// Mitsubishi GX Works2 project: Yuwakashi   PLC: Q00J

PROGRAM MAIN
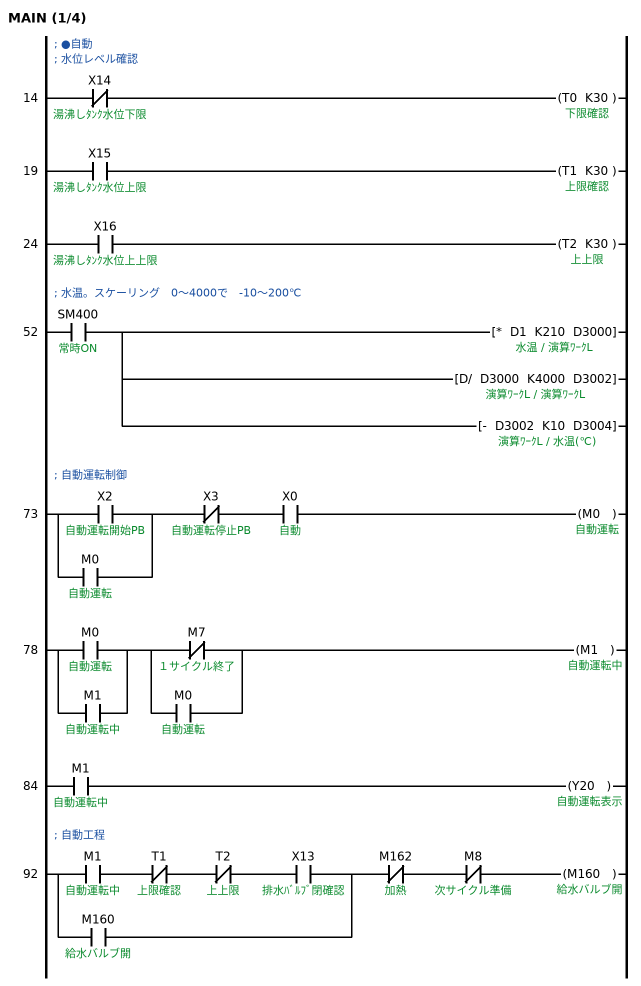
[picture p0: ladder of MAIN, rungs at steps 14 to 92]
; ●自動
; 水位レベル確認
14    LDI     X14  ; 湯沸しﾀﾝｸ水位下限
      OUT     T0 K30  ; 下限確認
19    LD      X15  ; 湯沸しﾀﾝｸ水位上限
      OUT     T1 K30  ; 上限確認
24    LD      X16  ; 湯沸しﾀﾝｸ水位上上限
      OUT     T2 K30  ; 上上限
; 水温。スケーリング　0～4000で　-10～200℃
52    LD      SM400  ; 常時ON
      *       D1 K210 D3000  ; 水温 / 演算ﾜｰｸL
      D/      D3000 K4000 D3002  ; 演算ﾜｰｸL
      -       D3002 K10 D3004  ; 水温(℃)
; 自動運転制御
73    LD      X2  ; 自動運転開始PB
      OR      M0  ; 自動運転
      ANI     X3  ; 自動運転停止PB
      AND     X0  ; 自動
      OUT     M0  ; 自動運転
78    LD      M0  ; 自動運転
      OR      M1  ; 自動運転中
      LDI     M7  ; １サイクル終了
      OR      M0  ; 自動運転
      ANB
      OUT     M1  ; 自動運転中
84    LD      M1  ; 自動運転中
      OUT     Y20  ; 自動運転表示
; 自動工程
92    LD      M1  ; 自動運転中
      ANI     T1  ; 上限確認
      ANI     T2  ; 上上限
      AND     X13  ; 排水ﾊﾞﾙﾌﾞ閉確認
      OR      M160  ; 給水バルブ開
      ANI     M162  ; 加熱
      ANI     M8  ; 次サイクル準備
      OUT     M160  ; 給水バルブ開
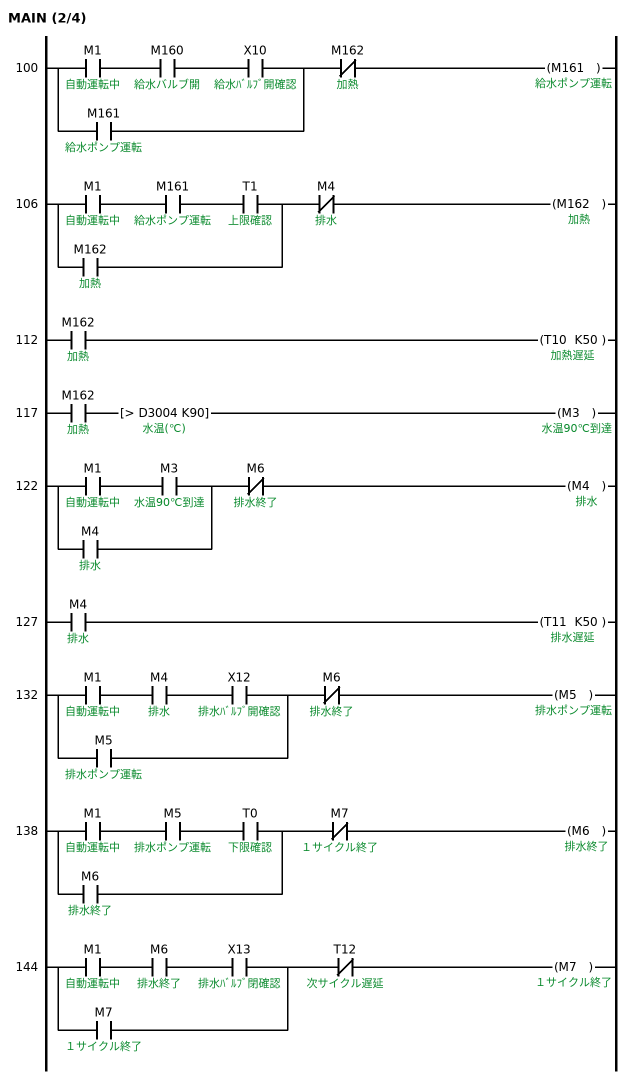
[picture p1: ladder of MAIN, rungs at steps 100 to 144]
100   LD      M1  ; 自動運転中
      AND     M160  ; 給水バルブ開
      AND     X10  ; 給水ﾊﾞﾙﾌﾞ開確認
      OR      M161  ; 給水ポンプ運転
      ANI     M162  ; 加熱
      OUT     M161  ; 給水ポンプ運転
106   LD      M1  ; 自動運転中
      AND     M161  ; 給水ポンプ運転
      AND     T1  ; 上限確認
      OR      M162  ; 加熱
      ANI     M4  ; 排水
      OUT     M162  ; 加熱
112   LD      M162  ; 加熱
      OUT     T10 K50  ; 加熱遅延
117   LD      M162  ; 加熱
      AND>    D3004 K90  ; 水温(℃)
      OUT     M3  ; 水温90℃到達
122   LD      M1  ; 自動運転中
      AND     M3  ; 水温90℃到達
      OR      M4  ; 排水
      ANI     M6  ; 排水終了
      OUT     M4  ; 排水
127   LD      M4  ; 排水
      OUT     T11 K50  ; 排水遅延
132   LD      M1  ; 自動運転中
      AND     M4  ; 排水
      AND     X12  ; 排水ﾊﾞﾙﾌﾞ開確認
      OR      M5  ; 排水ポンプ運転
      ANI     M6  ; 排水終了
      OUT     M5  ; 排水ポンプ運転
138   LD      M1  ; 自動運転中
      AND     M5  ; 排水ポンプ運転
      AND     T0  ; 下限確認
      OR      M6  ; 排水終了
      ANI     M7  ; １サイクル終了
      OUT     M6  ; 排水終了
144   LD      M1  ; 自動運転中
      AND     M6  ; 排水終了
      AND     X13  ; 排水ﾊﾞﾙﾌﾞ閉確認
      OR      M7  ; １サイクル終了
      ANI     T12  ; 次サイクル遅延
      OUT     M7  ; １サイクル終了
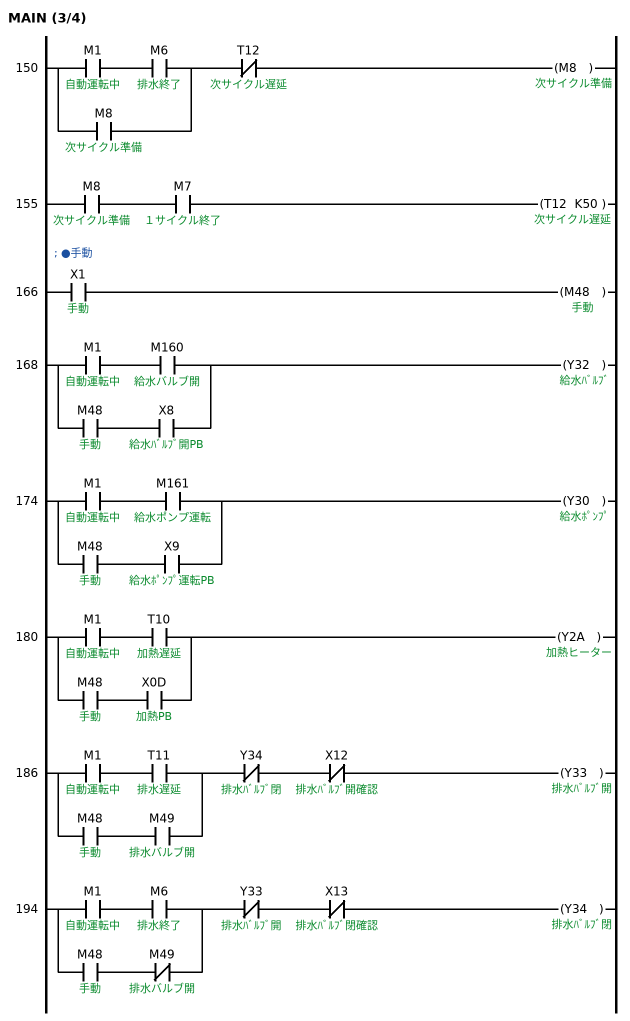
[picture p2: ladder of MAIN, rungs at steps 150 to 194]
150   LD      M1  ; 自動運転中
      AND     M6  ; 排水終了
      OR      M8  ; 次サイクル準備
      ANI     T12  ; 次サイクル遅延
      OUT     M8  ; 次サイクル準備
155   LD      M8  ; 次サイクル準備
      AND     M7  ; １サイクル終了
      OUT     T12 K50  ; 次サイクル遅延
; ●手動
166   LD      X1  ; 手動
      OUT     M48  ; 手動
168   LD      M1  ; 自動運転中
      AND     M160  ; 給水バルブ開
      LD      M48  ; 手動
      AND     X8  ; 給水ﾊﾞﾙﾌﾞ開PB
      ORB
      OUT     Y32  ; 給水ﾊﾞﾙﾌﾞ
174   LD      M1  ; 自動運転中
      AND     M161  ; 給水ポンプ運転
      LD      M48  ; 手動
      AND     X9  ; 給水ﾎﾟﾝﾌﾟ運転PB
      ORB
      OUT     Y30  ; 給水ﾎﾟﾝﾌﾟ
180   LD      M1  ; 自動運転中
      AND     T10  ; 加熱遅延
      LD      M48  ; 手動
      AND     X0D  ; 加熱PB
      ORB
      OUT     Y2A  ; 加熱ヒーター
186   LD      M1  ; 自動運転中
      AND     T11  ; 排水遅延
      LD      M48  ; 手動
      AND     M49  ; 排水バルブ開
      ORB
      ANI     Y34  ; 排水ﾊﾞﾙﾌﾞ閉
      ANI     X12  ; 排水ﾊﾞﾙﾌﾞ開確認
      OUT     Y33  ; 排水ﾊﾞﾙﾌﾞ開
194   LD      M1  ; 自動運転中
      AND     M6  ; 排水終了
      LD      M48  ; 手動
      ANI     M49  ; 排水バルブ開
      ORB
      ANI     Y33  ; 排水ﾊﾞﾙﾌﾞ開
      ANI     X13  ; 排水ﾊﾞﾙﾌﾞ閉確認
      OUT     Y34  ; 排水ﾊﾞﾙﾌﾞ閉
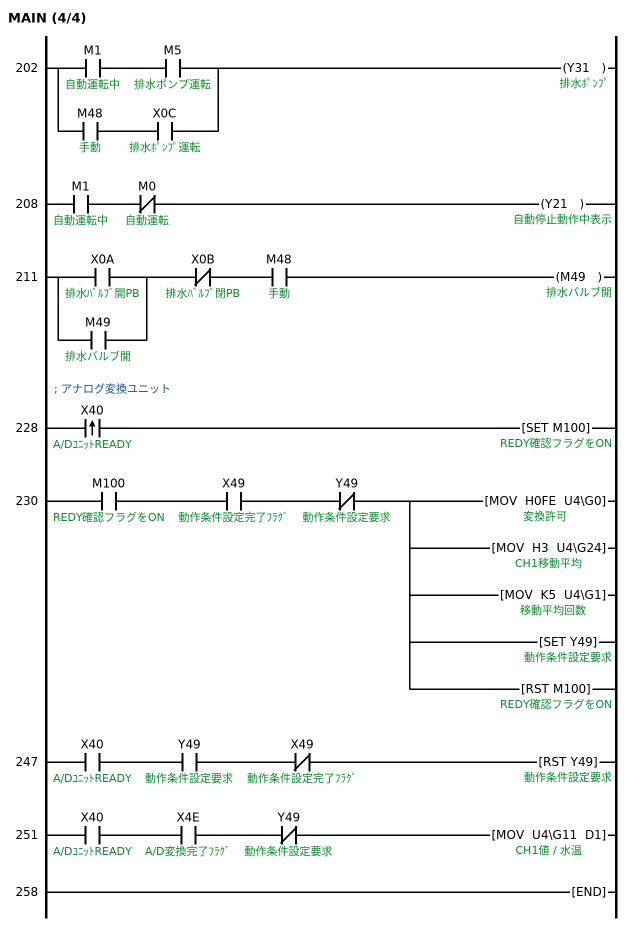
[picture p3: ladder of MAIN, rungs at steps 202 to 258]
202   LD      M1  ; 自動運転中
      AND     M5  ; 排水ポンプ運転
      LD      M48  ; 手動
      AND     X0C  ; 排水ﾎﾟﾝﾌﾟ運転
      ORB
      OUT     Y31  ; 排水ﾎﾟﾝﾌﾟ
208   LD      M1  ; 自動運転中
      ANI     M0  ; 自動運転
      OUT     Y21  ; 自動停止動作中表示
211   LD      X0A  ; 排水ﾊﾞﾙﾌﾞ開PB
      OR      M49  ; 排水バルブ開
      ANI     X0B  ; 排水ﾊﾞﾙﾌﾞ閉PB
      AND     M48  ; 手動
      OUT     M49  ; 排水バルブ開
; アナログ変換ユニット
228   LDP     X40  ; A/DﾕﾆｯﾄREADY
      SET     M100  ; REDY確認フラグをON
230   LD      M100  ; REDY確認フラグをON
      AND     X49  ; 動作条件設定完了ﾌﾗｸﾞ
      ANI     Y49  ; 動作条件設定要求
      MOV     H0FE U4\G0  ; 変換許可
      MOV     H3 U4\G24  ; CH1移動平均
      MOV     K5 U4\G1  ; 移動平均回数
      SET     Y49  ; 動作条件設定要求
      RST     M100  ; REDY確認フラグをON
247   LD      X40  ; A/DﾕﾆｯﾄREADY
      AND     Y49  ; 動作条件設定要求
      ANI     X49  ; 動作条件設定完了ﾌﾗｸﾞ
      RST     Y49  ; 動作条件設定要求
251   LD      X40  ; A/DﾕﾆｯﾄREADY
      AND     X4E  ; A/D変換完了ﾌﾗｸﾞ
      ANI     Y49  ; 動作条件設定要求
      MOV     U4\G11 D1  ; CH1値
258   END
END_PROGRAM
